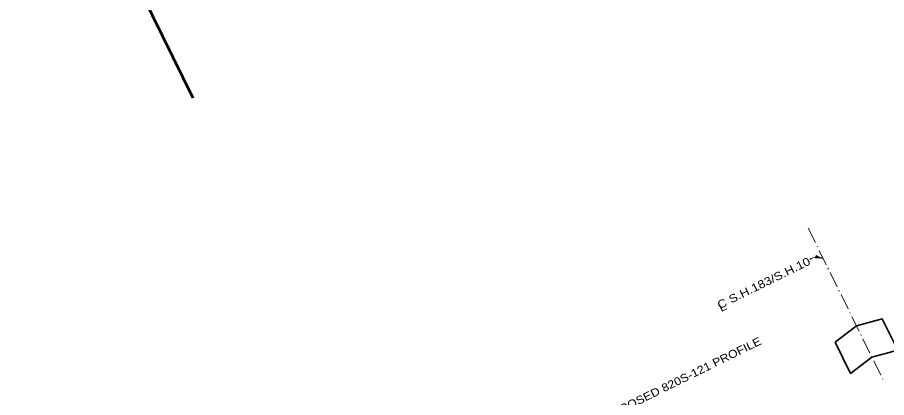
# Model space of a CAD drawing. Extents: x 2356431 to 2371438, y 6972864 to 6982525.
# Drawn here: x 2365783 to 2367303, y 6978229 to 6978894 of the extents above; entities that cross this region are included whole.
import ezdxf
from ezdxf.enums import TextEntityAlignment as Align

# ---------------------------------------------------------------- set-up
doc = ezdxf.new("R2010")
doc.units = 0
doc.header["$LTSCALE"] = 5.6
doc.linetypes.add('DOT_DASHED', pattern=[7.7, 5, -1.2, 0.3, -1.2])
for name, color, linetype, lineweight in [('1', 7, 'Continuous', 25), ('2', 7, 'Continuous', 35), ('44', 7, 'Continuous', 13), ('55', 7, 'Continuous', 13)]:
    doc.layers.add(name, color=color, linetype=linetype, lineweight=lineweight)

msp = doc.modelspace()

# ---------------------------------------------------------------- linework, layer by layer
at = {"layer": '1', "lineweight": 53}
msp.add_line((2365274.698, 6980404.566), (2366089.834, 6978752.959), dxfattribs=at)
at = {"layer": '1', "lineweight": 35}
msp.add_lwpolyline([(2367212.518, 6978325.882), (2367249.95, 6978354.503), (2367295.068, 6978366.623), (2367322.19, 6978311.779), (2367276.972, 6978299.633), (2367239.664, 6978271.105)], close=True, dxfattribs=at)
at = {"layer": '1', "lineweight": 13}
msp.add_arc((2367181.234, 6978450.966), 23.447, 63.53113, 124.1556, dxfattribs=at)
at = {"layer": '44', "linetype": 'DOT_DASHED'}
msp.add_line((2367165.58, 6978525.046), (2367298.356, 6978256.014), dxfattribs=at)
at = {"layer": '55'}
for p, q in [((2367178.322, 6978473.485), (2367179.296, 6978477.19)), ((2367178.411, 6978473.824), (2367179.945, 6978473.421)), ((2367178.538, 6978474.307), (2367182.674, 6978473.221)), ((2367178.665, 6978474.791), (2367185.774, 6978472.923)), ((2367178.792, 6978475.273), (2367190.944, 6978472.082)), ((2367178.919, 6978475.758), (2367187.247, 6978473.571)), ((2367179.046, 6978476.242), (2367183.749, 6978475.006)), ((2367179.173, 6978476.726), (2367181.477, 6978476.12))]:
    msp.add_line(p, q, dxfattribs=at)
for centre, start, end in [((2367176.827, 6978401.284), 78.12772, 88.81378), ((2367213.471, 6978540.806), 241.75456, 252.44061)]:
    msp.add_arc(centre, 72.216, start, end, dxfattribs=at)

# ---------------------------------------------------------------- texts
at = {"layer": '1'}
for s, height, width, p in [('C S.H.183/S.H.10', 14, 1.2, (2367090.806, 6978422.902)), ('L', 12, 1.4, (2367018.99, 6978381.242))]:
    msp.add_text(s, height=height, rotation=26.268, dxfattribs=dict(at, width=width)).set_placement(p, align=Align.CENTER)
at = {"layer": '2', "width": 1.15}
msp.add_text('PROPOSED 820S-121 PROFILE', height=14, rotation=26.268, dxfattribs=at).set_placement((2366941.777, 6978252.151), align=Align.CENTER)

doc.saveas('drawing.dxf')
